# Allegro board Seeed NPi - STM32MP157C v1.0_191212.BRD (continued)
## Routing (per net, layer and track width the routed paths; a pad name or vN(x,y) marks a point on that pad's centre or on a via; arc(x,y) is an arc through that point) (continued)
SDMMC1_CK: length 3.2
  TOP w0.121: J10.38 30.61,45.6 30.59,45.57 C11.1 29.63,45.57 29.61,45.55 R37.1
SDMMC1_CMD: length 57.6
  TOP w0.121: J10.36 31.28,46 30.32,46.96 28.48,46.96 26.45,48.99 22.13,48.99 19.2,51.92 14.28,51.92 14.28,51.93 14.27,51.93 12.86,53.34 8.71,53.34 8.16,53.88 8.16,54.33 8.16,54.33 8.16,54.46 v1(7.91,54.71)
  LYR3 w0.121: v1(7.91,54.71) 7.66,54.96 7.66,56.62 7.91,56.87 7.91,62.94 14.84,69.87 14.84,77.36 14.51,77.7 14.51,79.54 v1(14.92,79.95)
  BOTTOM w0.121: R154.1 v1(14.92,79.95)
SDMMC1_D0: length 51.6
  TOP w0.121: v1(41.69,54.84) 41.18,54.33 37.24,54.33 36.36,53.44 34.32,53.44 33.56,52.67 33.56,47.88 33.28,47.6 J10.28
  LYR3 w0.121: v1(40.62,79.65) 40.62,78.94 40.44,78.76 40.1,78.76 39.98,78.88 39.98,79.4 39.86,79.52 39.62,79.52 39.5,79.4 39.5,78.88 39.38,78.76 39,78.76 38.77,78.53 38.77,77.87 38.89,77.75 39.05,77.75 39.17,77.63 39.17,77.39 39.05,77.27 38.89,77.27 38.77,77.15 38.77,76.88 38.65,76.76 38.36,76.76 38.24,76.64 38.24,76.4 38.36,76.28 38.65,76.28 38.77,76.16 38.77,75.76 38.08,75.08 37.91,75.08 37.73,75.26 37.56,75.26 37.39,75.09 37.39,74.92 37.57,74.74 37.57,74.57 37.4,74.39 37.4,74.05 37.28,73.93 37.14,73.93 37.02,73.81 37.02,73.56 37.14,73.44 37.28,73.44 37.4,73.32 37.4,73.08 37.28,72.96 37.14,72.96 37.02,72.84 37.02,72.6 37.14,72.48 37.28,72.48 37.4,72.36 37.4,72.12 37.28,72 37.14,72 37.02,71.87 37.02,71.63 37.14,71.51 37.28,71.51 37.4,71.39 37.4,71.07 38.01,70.46 40.09,70.46 41.33,69.21 41.33,68.81 41.21,68.69 41.07,68.69 40.95,68.57 40.95,68.33 41.07,68.21 41.21,68.21 41.33,68.09 41.33,67.84 41.21,67.72 41.07,67.72 40.95,67.6 40.95,67.36 41.07,67.24 41.21,67.24 41.33,67.12 41.33,64.77 41.05,64.49 41.05,57.5 41.69,56.87 v1(41.69,54.84)
  BOTTOM w0.121: v1(40.62,79.65) 40.62,80.04 R83.1
SDMMC1_D1: length 54.8
  TOP w0.121: v1(42.71,54.84) 41.95,54.08 37.35,54.08 36.39,53.12 34.39,53.12 33.81,52.54 33.81,50.6 33.82,50.59 33.82,47.72 33.29,47.2 J10.30
  LYR3 w0.121: v1(39.53,78.28) 39.53,77.91 39.65,77.79 39.94,77.79 40.06,77.67 40.06,77.43 39.94,77.31 39.65,77.31 39.53,77.19 39.53,76.95 39.65,76.83 39.94,76.83 40.06,76.7 40.06,76.46 39.94,76.34 39.65,76.34 39.53,76.22 39.53,75.92 37.75,74.14 37.75,71.35 38.13,70.96 40.42,70.96 41.69,69.69 41.69,64.3 41.57,64.18 41.48,64.18 41.36,64.06 41.36,63.82 41.48,63.7 41.57,63.7 41.69,63.58 41.69,63.33 41.57,63.21 41.48,63.21 41.36,63.09 41.36,62.85 41.48,62.73 41.57,62.73 41.69,62.61 41.69,62.37 41.57,62.25 41.48,62.25 41.36,62.13 41.36,61.89 41.48,61.77 41.57,61.77 41.69,61.65 41.69,61.4 41.57,61.28 41.48,61.28 41.36,61.16 41.36,60.92 41.48,60.8 41.57,60.8 41.69,60.68 41.69,60.44 41.57,60.32 41.48,60.32 41.36,60.2 41.36,59.96 41.48,59.84 41.57,59.84 41.69,59.71 41.69,59.47 41.57,59.35 41.48,59.35 41.36,59.23 41.36,58.99 41.48,58.87 41.57,58.87 41.69,58.75 41.69,58.39 41.44,58.14 41.44,57.52 42.1,56.87 42.1,56.62 42.22,56.5 44.31,56.5 44.43,56.38 44.43,56.14 44.31,56.01 43.71,56.01 43.59,55.89 43.59,55.34 43.47,55.22 43.23,55.22 43.1,55.34 43.1,55.89 42.98,56.01 42.22,56.01 42.1,55.89 42.1,55.06 42.32,54.84 v1(42.71,54.84)
  BOTTOM w0.121: R93.1 39.14,78.24 39.18,78.28 v1(39.53,78.28)
SDMMC1_D2: length 54.4
  TOP w0.121: v1(8.42,55.47) 8.67,55.22 8.67,54.07 8.82,53.92 12.98,53.92 14.48,52.42 19.67,52.42 22.51,49.58 26.61,49.58 28.73,47.47 30.51,47.47 31.18,46.8 J10.32
  LYR3 w0.121: v1(8.42,55.47) 8.42,62.71 15.48,69.78 16.82,69.78 17.81,70.77 17.81,75.98 17.89,76.06 v1(17.89,76.41)
  BOTTOM w0.121: v1(17.89,76.41) 17.9,76.42 R142.1
SDMMC1_D3: length 54.8
  TOP w0.121: v1(8.03,55.85) 8.03,55.22 8.42,54.84 8.42,53.98 8.78,53.62 12.93,53.62 14.37,52.17 14.38,52.17 14.38,52.17 19.46,52.17 22.39,49.25 26.58,49.25 28.61,47.22 30.42,47.22 31.23,46.4 J10.34
  LYR3 w0.121: v1(14.98,77.95) 14.98,77.6 15.13,77.45 15.13,69.8 8.16,62.84 8.16,56.77 8.03,56.64 v1(8.03,55.85)
  BOTTOM w0.121: R156.1 15.02,77.99 v1(14.98,77.95)
SDMMC3_CLK: length 47.1
  TOP w0.121: v1(33.69,39.09) 34.04,39.09 34.15,39.2 J10.69 ; R26.1 27.05,68.72 26.82,68.94 v1(26.65,68.94)
  LYR3 w0.121: v1(34.58,68.68) 34.58,68.33 34.04,67.79 34.04,64.39 36.36,62.07 36.36,59.59 39.78,56.17 39.78,48.55 38.86,47.63 36.38,47.63 35.5,46.74 35.5,40.26 34.32,39.09 v1(33.69,39.09)
  LYR4 w0.121: v1(26.65,68.94) 27.29,68.3 34.2,68.3 v1(34.58,68.68)
SDMMC3_CMD: length 46.3
  TOP w0.121: v1(34.2,39.6) J10.67 ; v1(26.65,69.71) R25.1
  LYR3 w0.121: v1(34.2,39.6) 34.96,40.36 34.96,44.68 35.28,45 35.28,46.84 36.29,47.85 38.77,47.85 39.53,48.61 39.53,56.11 36.12,59.51 36.12,61.93 33.82,64.23 33.82,68.45 34.45,69.09 v1(34.45,69.44)
  LYR4 w0.121: v1(34.45,69.44) 33.69,68.68 29.5,68.68 29.09,69.09 27.27,69.09 v1(26.65,69.71)
SDMMC3_D0: length 50.7
  TOP w0.121: J10.59 34.12,41.2 v1(33.56,41.75) ; R27.1 26.77,67.78 26.19,68.36 26.19,70.34 25.56,70.96 v1(25.56,71.35)
  LYR3 w0.121: v1(33.31,70.67) 32.8,70.16 32.8,62.95 33.53,62.22 33.53,61.66 34.96,60.23 34.96,59.28 38.01,56.23 38.01,48.99 37.86,48.85 36.71,48.85 36.56,48.99 34.96,48.99 32.95,46.98 32.95,44.29 33.94,43.3 33.94,42.14 v1(33.56,41.75)
  LYR4 w0.121: v1(33.31,70.67) 32.84,70.2 28.51,70.2 28,70.71 26.2,70.71 v1(25.56,71.35)
SDMMC3_D1: length 51
  TOP w0.121: R28.1 26.03,66.81 25.44,67.4 25.44,70.6 v1(24.8,71.24) ; J10.61 33.75,40.8 v1(33.69,40.74)
  LYR3 w0.121: v1(33.69,40.74) 34.2,41.25 34.2,44.93 34.58,45.31 34.58,47.09 36.1,48.61 38.01,48.61 38.26,48.87 38.26,56.36 35.21,59.41 35.21,60.42 34.83,60.8 34.83,61.57 34.83,61.57 34.83,61.6 33.05,63.37 33.05,69.16 v1(33.3,69.41)
  LYR4 w0.121: v1(33.3,69.41) 32.95,69.41 32.85,69.31 28.35,69.31 27.57,70.1 25.94,70.1 v1(24.8,71.24)
SDMMC3_D2: length 46.6
  TOP w0.121: J10.63 v1(34.11,40.4) ; R23.1 v1(26.65,71.64)
  LYR3 w0.121: v1(34.45,70.71) 34.2,70.46 34.07,70.46 33.82,70.2 33.82,69.31 33.31,68.81 33.31,63.47 35.09,61.69 35.09,60.93 35.47,60.55 35.47,59.53 38.51,56.49 38.51,50.14 39.02,49.63 39.02,48.74 38.64,48.36 36.16,48.36 34.83,47.03 34.83,45.18 34.45,44.8 34.45,40.74 v1(34.11,40.4)
  LYR4 w0.121: v1(26.65,71.64) 26.94,71.35 33.82,71.35 v1(34.45,70.71)
SDMMC3_D3: length 48.5
  TOP w0.121: J10.65 v1(33.69,40) ; R24.1 26.77,70.7 26.25,71.22 v1(26.25,71.32)
  LYR3 w0.121: v1(33.69,40) 34.24,40 34.7,40.46 34.7,44.74 35.05,45.09 35.05,46.93 36.23,48.1 38.7,48.1 39.31,48.71 39.31,56.01 35.9,59.41 35.9,61.39 33.56,63.73 33.56,68.68 34.07,69.19 34.07,69.69 v1(34.45,70.08)
  LYR4 w0.121: v1(26.25,71.32) 26.52,71.04 33.48,71.04 v1(34.45,70.08)
SPI5_CLK: length 24.7
  TOP w0.121: v1(37.12,43.91) 36.89,43.91 36.81,44 J10.45
  LYR3 w0.121: v1(50.47,41.92) 50.22,42.17 50.22,42.17 49.44,42.96 49.44,47.92 50.23,48.71 J19.23
  LYR4 w0.121: v1(37.12,43.91) 37.6,43.91 37.72,44.04 40.17,44.04 40.8,43.41 48.93,43.41 50.14,42.2 50.2,42.2 50.22,42.17 50.22,42.17 v1(50.47,41.92)
SPI5_MISO: length 28.9
  TOP w0.121: J19.21 52.39,50.1 52.39,42.94 v1(53.22,42.1) ; v1(36.71,44.37) 36.36,44.37 36.33,44.4 J10.43
  LYR4 w0.121: v1(53.22,42.1) 52.87,42.1 52.67,42.31 50.53,42.31 49.21,43.63 40.96,43.63 40.21,44.37 v1(36.71,44.37)
SPI5_MOSI: length 32.4
  TOP w0.121: J10.41 36.36,44.8 36.38,44.77 v1(37.12,44.77) ; v1(53.93,42.44) 53.41,42.44 52.64,43.21 52.64,52.4 J19.19
  LYR4 w0.121: v1(37.12,44.77) 40.19,44.77 41.05,43.91 49.31,43.91 50.69,42.53 53.31,42.53 53.41,42.44 v1(53.93,42.44)
SPI5_NSS: length 20.1
  TOP w0.121: v1(37.63,50.01) 37.21,49.6 J10.17 34.66,49.6
  LYR4 w0.121: v1(37.63,50.01) 37.87,50.26 40.57,50.26 40.95,49.88 47.91,49.88 48.04,50.01 52.48,50.01 J19.24
STLINK_SWCLK: length 78.8
  TOP w0.121: v1(13.5,73.89) 13.5,74.24 13.11,74.63 13.11,75.59 13.94,76.42 R111.2 ; J7.53 42.48,49.6 40.18,47.3 v1(40.18,45.69)
  LYR3 w0.121: v1(7.65,50.64) 4.35,50.64 3.72,51.28 3.72,63.24 9.16,68.68 12.54,68.68 13.5,69.63 v1(13.5,73.89)
  LYR4 w0.121: v1(7.65,50.64) 7.65,48.99 8.67,47.98 11.84,47.98 12.7,47.12 20.3,47.12 23,44.42 34.2,44.42 35.21,45.44 38.32,45.44 38.57,45.69 v1(40.18,45.69)
STLINK_SWDIO: length 80.9
  TOP w0.121: R101.2 15.47,76.42 14.72,75.67 13.78,75.67 13.5,75.38 13.5,74.9 v1(13.88,74.52) ; v1(39.78,45.31) 40.33,45.31 40.55,45.54 40.55,47.27 42.48,49.2 J7.51
  LYR3 w0.121: v1(7.53,51.41) 7.17,51.41 7.05,51.53 4.48,51.53 3.97,52.04 3.97,63.13 9.26,68.42 12.6,68.42 13.72,69.54 13.72,73.22 13.88,73.38 v1(13.88,74.52)
  LYR4 w0.121: v1(7.53,51.41) 7.15,51.03 7.15,48.1 9.18,46.07 12.48,46.07 13.31,46.9 18.48,46.9 20.44,44.93 21.62,44.93 22.39,44.17 34.26,44.17 35.27,45.18 39.3,45.18 39.43,45.31 v1(39.78,45.31)
SW: length 1.2
  BOTTOM w0.305: U9.6 v1(36.34,23.58)
  vias: v1(31.02,27.28) v1(31.02,26.77) v1(31.53,27.28) v1(31.53,26.77) v1(32.04,27.28) v1(32.04,26.77) v1(36.61,23.97) v1(36.86,23.59) v1(37.12,23.97)
TIM1_CH4: length 47.3
  TOP w0.121: J14.46 21.95,54.89 23.26,53.58 v1(23.26,52.18)
  LYR4 w0.121: v1(46.26,54.45) 43.59,54.45 42.96,53.82 39.02,53.82 37.38,52.18 v1(23.26,52.18)
  BOTTOM w0.121: J19.31 50.07,39.72 50.07,42.64 48.29,44.43 48.29,46.08 47.79,46.57 47.03,46.57 46.01,47.6 46.01,53.84 46.26,54.09 v1(46.26,54.45)
TIM4_CH3: length 19.4
  TOP w0.121: J7.35 41.99,46 41.43,45.43 41.43,42.01 v1(41.82,41.63)
  LYR4 w0.121: J19.32 52.36,39.98 50.2,39.98 48.55,41.63 v1(41.82,41.63)
TIM4_CH4: length 21.3
  TOP w0.121: v1(41.56,37.06) 41.18,37.44 41.18,45.56 42.01,46.4 J7.37
  LYR4 w0.121: v1(41.56,37.06) 42.6,36.01 J19.33
TIM5_CH4: length 50.2
  TOP w0.121: v1(18.45,54.45) 16.92,54.45 16.66,54.71 16.66,55.52 16.75,55.61 J14.20
  LYR4 w0.121: v1(18.45,54.45) 19.59,54.45 19.85,54.2 30.01,54.2 31.78,55.98 44.36,55.98 44.79,56.41 46.11,56.41 v1(46.36,56.16)
  BOTTOM w0.121: J19.29 51.24,42.11 48.57,44.77 48.57,46.17 47.92,46.82 47.16,46.82 46.77,47.21 46.77,54.84 46.36,55.25 v1(46.36,56.16)
UART4_RX: length 48
  TOP w0.121: v1(47.14,18.14) R97.2 46.76,18.8 46.73,18.77 44.74,18.77 44.48,19.03 U6.6 ; J10.27 36.56,47.6 37.07,47.09 37.17,47.09 v1(37.21,47.05)
  LYR3 w0.121: v1(48.17,30.07) 44.23,26.13 44.23,21.05 v1(47.14,18.14)
  BOTTOM w0.121: v1(37.21,47.05) 37.68,46.57 45,46.57 49.31,42.26 49.31,31.21 v1(48.17,30.07)
UART4_TX: length 39.2
  TOP w0.121: U6.5 44.98,19.41 45.12,19.28 46.65,19.28 47.15,19.78 R98.2 47.15,20.42 44.74,22.83 44.74,25.63 49.56,30.45 49.56,49.63 49.2,50 J7.56
USART1_CTS: length 31.7
  TOP w0.121: v1(38.13,43.62) 37.37,42.86 37.37,42.26 37.11,42 J10.55
  LYR3 w0.121: v1(38.13,43.62) 38.13,44.68 41.56,48.1 41.56,50.14 40.55,51.15 40.55,56.49 39.91,57.12 39.91,67.91 40.17,68.17 v1(40.17,68.57)
  BOTTOM w0.121: R79.1 40.42,68.94 40.17,68.68 v1(40.17,68.57)
USART1_RTS: length 37.8
  TOP w0.121: v1(38.13,43.02) 38.13,42.64 37.09,41.6 J10.57
  LYR3 w0.121: v1(38.77,69.69) 39.12,70.05 39.68,70.05 40.54,69.19 40.54,68.16 40.17,67.79 40.17,57.25 40.77,56.64 40.77,51.31 41.82,50.26 41.82,47.98 38.51,44.67 38.51,43.4 v1(38.13,43.02)
  BOTTOM w0.121: v1(38.77,69.69) 39.56,70.49 39.56,71.61 40.04,72.09 R76.1
USART1_RX: length 32.2
  TOP w0.121: J10.53 36.5,42.4 36.51,42.39 v1(36.86,42.39)
  LYR3 w0.121: v1(36.86,42.39) 37.75,43.28 37.75,44.68 41.28,48.2 41.28,48.33 41.31,48.36 41.31,50.01 40.29,51.02 40.29,56.36 39.66,56.99 v1(39.66,68.3)
  BOTTOM w0.121: v1(39.66,68.3) 39.66,68.4 39.78,68.52 39.78,69.44 40.42,70.08 R78.1
USART1_TX: length 33.6
  TOP w0.121: v1(38.01,46.2) 38.01,44.04 36.76,42.8 J10.51
  LYR3 w0.121: v1(39.45,69.61) 39.2,69.37 39.2,57.07 40.04,56.23 40.04,50.9 41.05,49.88 41.05,48.36 38.9,46.2 v1(38.01,46.2)
  BOTTOM w0.121: v1(39.45,69.61) 39.45,69.97 39.81,70.32 39.81,70.99 39.95,71.13 R77.1
USART2_CTS: length 59.5
  TOP w0.121: J14.48 22.35,55.1 24.04,53.42 24.04,52.32 v1(23.26,51.54)
  LYR4 w0.121: v1(52.48,54.45) 52.1,54.84 43.34,54.84 42.58,54.07 38.93,54.07 37.41,52.55 22.9,52.55 22.77,52.42 22.77,51.69 22.91,51.54 v1(23.26,51.54)
  BOTTOM w0.121: v1(52.48,54.45) 52.74,54.2 52.74,54.07 52.77,54.04 52.77,34.49 J19.36
USART2_RTS: length 21.3
  TOP w0.121: v1(48.28,48.22) 47.93,48.22 47.92,48.23 47.91,48.23 47.75,48.4 J7.48
  LYR3 w0.121: J19.11 52.51,62.68 52.51,60.42 52,59.92 50.71,59.92 48.67,57.88 48.67,53.82 49.18,53.31 49.18,50.77 48.28,49.87 v1(48.28,48.22)
USART2_RX: length 34.8
  TOP w0.121: J10.2 31.79,52.8 31.66,52.93 31.66,55.02 32.99,56.36 43.47,56.36 47.15,60.04 v1(48.93,60.04)
  LYR4 w0.121: J19.10 52.61,67.66 50.2,67.66 49.82,67.28 49.82,60.3 49.56,60.04 v1(48.93,60.04)
USART2_TX: length 35.9
  TOP w0.121: v1(49.31,60.55) 47.02,60.55 43.09,56.61 32.9,56.61 31.28,54.99 31.28,52.62 31.5,52.4 J10.4
  LYR4 w0.121: v1(49.31,60.55) 49.56,60.8 49.56,67.66 49.82,67.92 52.66,67.92 J19.8
USB1_EN: length 67.5
  TOP w0.121: v1(21.12,54.96) 21.12,55.31 21.13,55.33 21.13,55.35 21.15,55.37 J14.42 ; v1(24.16,23.59) 22.64,22.07 17.18,22.07 16.04,23.21 16.04,27.02 v1(15.27,27.78)
  LYR3 w0.121: v1(15.27,27.78) 11.08,31.98 11.08,35.23 9.05,37.26 v1(9.05,40.48)
  LYR4 w0.121: v1(21.12,54.96) 21.12,55.72 19.85,56.99 7.83,56.99 5.53,54.69 5.53,44.01 v1(9.05,40.48)
  BOTTOM w0.121: U12.3 24.06,23.69 v1(24.16,23.59) 24.19,23.56 R20.2
USB1_N: length 62.8
  TOP w0.114: J7.62 47.18,51.2 47.24,51.26 47.68,51.26 v1(47.91,51.03) ; v1(18.33,24.23) 18.58,24.47 18.58,30.58 20.1,32.1 23.91,32.1 27.59,35.79 38.51,35.79 38.99,35.31 38.99,34.92 v1(39.23,34.67)
  LYR3 w0.127: v1(39.23,34.67) 39,34.91 39,35.33 47.02,43.35 47.02,44.01 47.15,44.14 47.15,44.14 47.28,44.27 47.28,44.52 47.15,44.65 47.15,44.65 47.02,44.78 47.02,45.03 47.15,45.16 47.15,45.16 47.28,45.28 47.28,45.54 47.15,45.67 47.15,45.67 47.02,45.79 47.02,50.97 47.29,51.24 47.69,51.24 v1(47.91,51.03)
  BOTTOM w0.114: v1(18.33,24.23) 18.58,23.98 18.58,21.82 18.07,21.31 16.53,21.31 14.5,19.28 14.5,18.6 14.21,18.31 L4.1 14.12,17.69 R72.1
USB1_OC: length 53.4
  TOP w0.121: J14.40 20.75,55.61 20.73,55.59 v1(20.73,55.36)
  LYR4 w0.121: v1(17.94,28.29) 15.78,28.29 14.38,29.69 14.38,35.79 5.75,44.42 5.75,54.5 7.98,56.74 19.36,56.74 v1(20.73,55.36)
  BOTTOM w0.121: U12.8 17.53,26.23 17.81,26.51 17.81,27.6 17.56,27.85 R10.1 v1(17.94,28.29)
USB1_P: length 62.8
  TOP w0.114: v1(38.47,34.67) 38.71,34.92 38.71,35.19 38.4,35.51 37.57,35.51 37.46,35.39 37.46,35.26 37.34,35.15 37.12,35.15 37,35.26 37,35.39 36.89,35.51 36.66,35.51 36.54,35.39 36.54,35.26 36.43,35.15 36.2,35.15 36.09,35.26 36.09,35.39 35.97,35.51 27.71,35.51 24.03,31.82 20.22,31.82 18.85,30.46 18.85,24.47 v1(19.1,24.23) ; v1(47.91,51.79) 47.66,51.54 47.24,51.54 47.18,51.6 J7.64
  LYR3 w0.127: v1(47.91,51.79) 47.67,51.55 47.17,51.55 46.72,51.1 46.72,43.48 38.7,35.46 38.7,34.91 v1(38.47,34.67)
  BOTTOM w0.114: R80.1 15.13,17.72 L4.4 15.06,18.31 14.78,18.6 14.78,19.16 16.65,21.03 18.18,21.03 18.85,21.7 18.85,23.98 v1(19.1,24.23)
USB2_EN: length 49.4
  TOP w0.121: J7.52 48.47,49.2 49.31,48.36 49.31,36.67 44.99,32.36 v1(41.31,32.36)
  LYR4 w0.121: v1(41.31,32.36) 33.43,24.48 26.7,24.48 24.16,21.94 v1(23.78,21.94)
  BOTTOM w0.121: U12.4 23.3,22.42 v1(23.78,21.94) 23.82,21.91 R17.2
USB2_N: length 60
  TOP w0.114: v1(48.37,52.21) 48.13,52.46 47.24,52.46 47.18,52.4 J7.68 ; v1(29.12,33.84) 28.87,34.1 27.82,34.1 24.53,30.81 22.6,30.81 22.49,30.69 22.49,30.62 22.37,30.5 22.14,30.5 22.03,30.62 22.03,30.69 21.91,30.81 21.49,30.81 21.15,30.47 21.15,30.15 20.98,29.99 20.67,29.99 19.97,29.29 19.97,23.46 v1(20.22,23.21)
  LYR3 w0.127: v1(48.37,52.21) 48.14,52.44 46.46,52.44 46.06,52.04 46.06,44.17 35.97,34.08 29.36,34.08 v1(29.12,33.84)
  BOTTOM w0.114: v1(20.22,23.21) 19.97,22.97 19.97,21.05 18.93,20.01 17.79,20.01 16.94,19.16 16.94,18.6 17.22,18.31 L5.2 17.24,17.77 R86.2
USB2_OC: length 61.9
  TOP w0.121: J7.50 48.24,48.8 49.06,47.97 49.06,36.81 44.99,32.74 v1(40.67,32.74)
  LYR4 w0.121: v1(40.67,32.74) 32.64,24.7 26.54,24.7 24.16,22.32 15.78,22.32 14.01,20.55 v1(14.01,19.53)
  BOTTOM w0.121: v1(14.01,19.53) R9.1 14.01,20.61 14,20.61 14,20.93 15.5,22.42 U12.5
USB2_P: length 60
  TOP w0.114: v1(29.12,34.63) 28.87,34.38 27.71,34.38 24.42,31.09 21.37,31.09 19.69,29.41 19.69,23.46 v1(19.45,23.21) ; J7.70 47.18,52.8 47.24,52.74 48.13,52.74 v1(48.37,52.98)
  LYR3 w0.127: v1(29.12,34.63) 29.36,34.39 35.85,34.39 45.75,44.29 45.75,52.17 46.33,52.75 48.14,52.75 v1(48.37,52.98)
  BOTTOM w0.114: v1(19.45,23.21) 19.69,22.97 19.69,21.17 18.82,20.29 17.67,20.29 16.66,19.28 16.66,18.6 16.37,18.31 L5.3 16.28,17.69 R87.2
VETH1_AVDDH: length 33.6
  TOP w0.305: v1(28.1,33.12) 28.1,32.67 27.85,32.42 27.85,25.75 27.21,25.12 27.21,20.55 23.83,17.17 23.83,13.89 28.89,8.83 v1(29.55,8.83)
  BOTTOM w0.305: U5.47 v1(20.59,41.99) ; U5.12 13.46,40.32 v1(13.24,40.1) ; U5.1 18.96,39.96 19.63,39.29 C52.1 20.36,39.29 v1(20.36,39.29)
  BOTTOM w0.381: R103.1 v1(29.55,8.83)
  vias: v1(28.1,33.63)
VETH1_AVDDL: length 1.4
  BOTTOM w0.305: U5.9 v1(14.96,40.1) ; U5.4 v1(17.46,40.07)
  vias: v1(14.26,38.58) v1(14.77,38.58)
VETH1_AVDDL_PLL: length 5.2
  BOTTOM w0.305: C43.1 23.47,43.71 C42.1 C41.1 20.91,43.71 20.69,43.49 U5.44
  BOTTOM w0.381: C43.1 23.61,43.69 FB9.2
VETH1_AVDDL_PMOS: length 2
  BOTTOM w0.381: v1(12.58,52.65) FB6.1 v1(13.06,52.24) ; v1(12.62,38.08) 12.63,38.07 12.86,38.07 12.95,37.98 R109.1 v1(13.11,38.58)
  vias: v1(25.18,43.02) v1(25.18,42.52) v1(25.69,42.52)
VETH1_DVDDH: length 64.3
  TOP w0.305: v1(29.6,7.95) 29.14,7.95 23.4,13.69 23.4,17.62 26.7,20.93 26.7,25.37 27.34,26.01 27.34,28.67 v1(26.2,29.82)
  LYR3 w0.305: v1(23.91,32.86) 23.91,32.1 v1(26.2,29.82)
  LYR3 w0.381: v1(23.91,32.86) 23.91,45.59 v1(23.1,46.4)
  BOTTOM w0.305: R89.1 22.31,45.69 R94.2 ; R108.1 22.35,37.31 22.89,36.76 22.89,35.79 22.5,35.39 U8.5 22.5,33.39 23.03,32.86 v1(23.91,32.86) C62.1 ; v1(29.6,7.95) R104.1 R102.1 ; U5.34 v1(17.96,48.46) ; R107.2 v1(10.12,43.28) R106.2 ; U5.40 v1(20.41,45.49) ; U5.16 v1(12.13,42.99)
  BOTTOM w0.381: R66.2 v1(17.86,50.72) ; R70.2 v1(18.88,50.69) ; R68.2 15.83,50.69 v1(15.91,50.77) ; R64.2 v1(14.82,50.72) ; R85.1 R74.1 v1(24.34,48.43) ; R69.2 v1(16.85,50.72) ; R65.2 13.8,50.59 13.75,50.64 v1(13.75,50.77) ; C34.1 v1(22.69,49.96) ; R89.1 v1(23.1,46.4) ; C30.1 22.3,50.99 22.64,50.64 v1(22.64,50.39)
VETH1_DVDDL: length 5.4
  BOTTOM w0.305: U5.26 13.96,48.18 13.66,48.49 13.26,48.49 v1(13.25,48.48) ; U5.18 v1(12.15,43.99) ; U5.14 v1(12.11,41.99) ; v1(20.35,46) 20.35,45.99 U5.39 ; U5.30 v1(15.96,48.49) ; U5.23 v1(12.14,46.49)
  BOTTOM w0.381: v1(12.79,48.69) 12.79,48.82 12.48,49.12 C33.1
WL_HOST_WAKE: length 35.9
  TOP w0.121: R19.2 19.85,74.39 v1(19.34,74.39) ; v1(30.13,72.49) 30.65,71.97 U3.13 ; J14.28 18.35,55.48 18.24,55.36 v1(17.89,55.36)
  LYR3 w0.121: v1(17.89,55.36) 17.89,59.73 19.34,61.19 19.34,64.23 19.85,64.74 19.85,69.31 19.34,69.82 v1(19.34,74.39)
  BOTTOM w0.121: v1(19.34,74.39) 19.59,74.14 21.12,74.14 21.5,73.76 21.5,72.87 21.88,72.49 v1(30.13,72.49)
WL_REG_ON: length 21.3
  TOP w0.121: R133.1 19.84,73 v1(19.85,73) ; v1(18.45,54.96) 18.58,54.96 18.75,55.14 J14.30
  LYR3 w0.121: v1(19.85,73) 19.62,72.77 19.62,69.85 20.1,69.37 20.1,64.61 19.59,64.11 19.59,61.06 18.19,59.66 18.19,55.85 18.45,55.6 v1(18.45,54.96)
N303234: length 8.1
  BOTTOM w0.381: R104.2 29.03,7.18 J13.11
N303238: length 8.2
  BOTTOM w0.381: R102.2 32.36,7.18 J13.14
N303440: length 6.6
  BOTTOM w0.121: X3.1 23.09,39.29 C51.2 22.5,39.29 22.26,39.53 22.26,39.9 21.61,40.56 R100.2 21.49,40.56 20.99,41.06 20.99,42.14 20.63,42.49 U5.46
N303536: length 8
  BOTTOM w0.121: U5.45 20.51,42.99 21.55,41.96 R100.1 21.61,41.32 22.14,40.8 22.26,40.8 22.5,40.56 C47.2 22.62,40.56 23.15,40.04 24.93,40.04 25.65,40.76 X3.3
N303624: length 8
  BOTTOM w0.381: J13.5 31.33,14.74 J13.6 31.33,12.45 31.17,12.3 C48.1 R103.2
N303732: length 2.6
  BOTTOM w0.121: U8.2 21.85,31.44 21.47,31.06 R128.2 R129.2
N3772447: length 8.9
  TOP w0.121: v1(38.26,69.19) 37.12,69.19 36.74,68.81 36.74,64.26 37.4,63.6 U3.28
  BOTTOM w0.121: v1(38.26,69.19) 38.84,69.19 TP6.1
N3772513: length 10.2
  TOP w0.121: U3.27 36.5,63.47 36.36,63.62 36.36,69.57 v1(36.86,70.08)
  BOTTOM w0.121: TP5.1 38.26,70.33 37.12,70.33 v1(36.86,70.08)
N3772517: length 7.2
  TOP w0.121: U3.26 35.6,63.47 35.6,63.48 35.6,65.76 35.9,66.06 v1(35.9,69.03)
  BOTTOM w0.121: v1(35.9,69.03) TP9.1
N3772521: length 9.2
  TOP w0.121: v1(35.85,70.08) 35.35,69.58 35.35,64.24 34.7,63.59 U3.25
  BOTTOM w0.121: TP8.1 36.1,70.58 36.1,70.32 v1(35.85,70.08)
N3772562: length 2.9
  TOP w0.121: v1(38.13,75.66) 38.39,75.66 39.2,74.85 U3.4
  BOTTOM w0.121: TP7.1 38.31,75.66 v1(38.13,75.66)
N3774700: length 5.6
  TOP w0.254: X1.1 24.82,72.69 25.78,73.65 28.02,73.65 28.38,73.29 C9.1 28.5,73.29 28.86,72.93 28.86,72.93 29.28,72.52 R30.2
N3775644: length 5.4
  TOP w0.381: R49.2 41.94,76.15 arc(41.28,75.87) 41,75.2 U3.2
N3776012: length 12.4
  TOP w0.121: v1(21.95,73.05) 21.5,73.5 R133.2 20.75,73.64 R22.2 ; v1(30.26,73.12) 30.51,72.87 U3.12
  BOTTOM w0.121: v1(30.26,73.12) 22.38,73.12 22.31,73.05 v1(21.95,73.05)
N3776054: length 4.5
  TOP w0.121: R23.2 27.91,71.58 28.33,71.16 29.45,71.16 29.87,71.57 ; U3.14 30.37,71.07 29.87,71.57 ; 29.87,71.57 R31.1
N3776279: length 4.5
  TOP w0.121: 29.87,70.61 30.41,70.61 30.85,70.17 U3.15 ; 29.87,70.61 29.46,70.19 28.36,70.19 27.91,70.64 R24.2 ; 29.87,70.61 R32.1
N3776286: length 4.4
  TOP w0.121: U3.16 30.69,69.27 30.26,69.7 R33.1 29.88,69.64 29.47,69.23 28.33,69.23 27.91,69.65 R25.2
N3776293: length 4.4
  TOP w0.121: R26.2 27.91,68.66 28.35,68.22 29.46,68.22 29.89,68.65 R34.1 30.27,68.71 30.61,68.37 U3.17
N3776300: length 4.4
  TOP w0.121: R27.2 27.91,67.72 28.37,67.26 29.46,67.26 29.89,67.69 R35.1 30.27,67.75 30.55,67.47 U3.18
N3776307: length 4.5
  TOP w0.121: U3.19 30.49,66.57 30.28,66.78 R36.1 29.9,66.46 29.74,66.31 28.36,66.31 27.91,66.75 R28.2
N3776951: length 2.7
  TOP w0.121: R38.1 34.3,60.58 33.8,61.08 U3.24
N3777387: length 3.1
  TOP w0.121: R42.1 39.75,60.21 38.3,61.66 U3.29
N3779189: length 6.2
  TOP w0.381: R51.1 44.82,75.38 45.82,74.38 arc(46.74,73) 47.07,71.38 C22.1 47.05,70.76 R52.2
N3779193: length 2.6
  TOP w0.381: J16.1 47.05,67.37 47.05,67.37 C21.1 47.05,68.3 R52.1
N3780208: length 5.2
  TOP w0.381: ANT1.1 46.42,80.37 46.41,80.36 R50.1 47.42,76.91 C23.1
N3780222: length 1.9
  TOP w0.381: R49.1 45.53,76.14 R50.2 47.13,76.14 arc(47.29,76.11) C24.1
N3787372: length 56.5
  TOP w0.121: J7.55 44.48,50 44.86,50.38 44.86,53.57 45.12,53.83 v1(49.31,53.83)
  LYR3 w0.121: v1(49.69,17.62) 47.53,19.78 46.26,19.78 44.61,21.43 44.61,25.88 48.99,30.26 48.99,49.06 49.56,49.62 49.56,53.58 v1(49.31,53.83)
  BOTTOM w0.121: TP2.1 52.71,14.6 v1(49.69,17.62)
N3787386: length 1.6
  TOP w0.121: J7.57 v1(44.35,50.4)
  BOTTOM w0.121: TP15.1 44.97,50.4 v1(44.35,50.4)
N3787400: length 55.7
  TOP w0.121: v1(49.31,54.45) 48.93,54.07 44.86,54.07 44.48,53.69 44.48,51.03 44.25,50.8 J7.59
  LYR3 w0.121: v1(49.31,54.45) 49.82,53.95 49.82,49.57 49.21,48.96 49.21,30.1 44.83,25.72 44.83,21.72 46.55,20.01 47.94,20.01 v1(49.69,18.26)
  BOTTOM w0.121: TP1.1 51.44,16.51 v1(49.69,18.26)
N3793884: length 2.1
  TOP w0.508: U3.21 30.57,64.77 30.54,64.74 L1.1
N3794135: length 12
  TOP w0.508: L1.2 27.13,63.93 v1(27.85,63.22) ; v1(33.31,60.55) 33.31,61.1 32.9,61.5 U3.23
  LYR4 w0.508: v1(33.31,60.55) 32.76,60.55 32.63,60.68 29.88,60.68 28.67,61.89 28.67,62.4 v1(27.85,63.22)
  BOTTOM w0.508: v1(33.31,60.55) 33.31,60.46 33.96,59.81 C49.1
N3820313: length 10
  LYR4 w0.305: v1(36.79,50.09) 32.11,50.09 31.53,49.5 28.61,49.5 v1(28.35,49.25)
  BOTTOM w0.305: R67.2 v1(36.79,50.09) ; C29.1 28.43,49.32 v1(28.35,49.25)
N3820535: length 22.5
  LYR4 w0.406: v1(23.9,50.02) 24.4,50.02 24.51,50.14 31.15,50.14 32.42,51.41 v1(34.2,51.41) 36.11,51.41 36.23,51.52 36.88,51.52 v1(37.5,50.9)
  BOTTOM w0.305: R75.1 36.19,51.99 36.82,51.36 36.93,51.36 37.08,51.21 37.18,51.21 v1(37.5,50.9)
  BOTTOM w0.406: C46.1 23.61,54.41 23.4,54.2 23.4,52.77 23.9,52.27 v1(23.9,50.02) ; U4.5 v1(34.2,51.41)
N3820638: length 3.5
  BOTTOM w0.305: U4.7 34.53,50.11 35.4,50.98 R71.1 35.4,52.03 R75.2
N3835690: length 10
  TOP w0.508: R110.1 v1(18.7,19.4)
  LYR3 w0.508: v1(18.7,19.4) v1(18.19,19.4) 18.16,19.4 16.79,18.04 J8.A4
N3835694: length 2.6
  TOP w0.508: R114.1 20.73,19.72 20.3,19.28 19.98,19.28 v1(19.59,18.89)
  vias: v1(19.62,19.35)
N3854640: length 2.6
  TOP w0.508: J11.14 31.5,78.23 31.53,78.2 ; 32.42,78.08 32.5,78.16 J11.15
N3854714: length 3.3
  BOTTOM w0.381: J22.15 7.58,58.07 7.78,58.26 ; J22.16 7.61,59.07 7.65,59.03
N3873950: length 3
  TOP w0.508: J2.B12 7.13,35.51 7.65,36.04 v1(7.65,36.42) ; J2.B1 6.5,29.05 v1(7.78,29.05)
  vias: v1(7.53,36.93) v1(7.78,28.55) v1(8.03,36.93) v1(8.29,29.05)
N3874122: length 8.2
  TOP w0.381: J2.B4 5.83,29.86 5.18,30.52 ; 5.42,34.16 5.93,34.66 J2.B9
  TOP w0.508: J2.B9 7.25,34.66 v1(7.53,34.39) ; 5.18,30.52 4.66,31.04 4.66,33.4 5.42,34.16
  vias: v1(7.53,34.9) v1(8.03,34.9) v1(8.03,34.39) v1(8.54,34.9) v1(8.54,34.39)
N3911606: length 9.8
  TOP w0.121: v1(11.84,77.82) 11.5,78.17 SW3.3 SW3.1 ; R167.1 v1(15.5,75.76)
  LYR4 w0.121: v1(11.84,77.82) 12.23,77.82 14.28,75.76 v1(15.5,75.76)
N3915722: length 2.5
  TOP w0.121: Q3.3 12.89,64.84 12.82,64.77 R5.1 12.32,64.77 12.01,65.08 11.89,65.08 11.45,65.52 R3.1
N3915999: length 2.9
  TOP w0.121: Q2.3 13.46,68.07 12.86,67.47 12.78,67.47 12.46,67.16 R7.1 12.34,67.16 12.03,66.85 11.94,66.85 11.76,66.67 11.76,66.61 11.45,66.3 R8.1
N3917680: length 6.5
  TOP w0.121: R15.2 16.8,71.35 17.56,70.58 20.35,70.58 20.57,70.8 J9.2
N3931666: length 5.8
  BOTTOM w0.254: 3.4,76 CON1.4 3.4,73.94 3.74,73.61 R176.2
N3973979: length 9.1
  TOP w0.121: J9.5 20.57,68.59 18.83,70.33 R16.1
N3987111: length 9.1
  TOP w0.121: R1.2 v1(1.91,17.09) ; v1(3.21,9.88) 3.21,9.13 LED1.1
  BOTTOM w0.121: v1(1.91,17.09) 1.91,11.17 v1(3.21,9.88)
N3987115: length 1.1
  TOP w0.121: R1.1 2.68,15.82 Q1.3
N3990987: length 4.3
  BOTTOM w0.121: 35.38,50.02 34.81,49.46 U4.8 ; 35.38,50.02 R67.1 ; 35.38,50.02 35.38,49.56 35.36,49.54 R161.1 35.36,48.56 35.34,48.55 R160.2
N3991147: length 5.6
  BOTTOM w0.121: C19.1 35.34,47.15 35.1,47.39 35.1,47.4 TP4.1 33.75,48.18 33.7,48.23 32.8,48.23 31.57,49.46 U4.1
N3991771: length 2.4
  BOTTOM w0.381: L2.1 34.34,54.47 34.7,54.84 v1(34.71,54.84)
  BOTTOM w0.406: U4.3 v1(29.62,50.76)
  vias: v1(28.74,51.28) v1(29.12,50.77) v1(29.24,51.28) v1(34.7,54.33) v1(34.7,53.82) v1(35.21,54.84) v1(35.21,54.33) v1(35.21,53.82)
N4046258: length 34
  LYR4 w0.305: v1(17.12,66.84) 18.12,65.83 26,65.83 27.85,63.98 39.61,63.98 v1(44.05,59.53)
  BOTTOM w0.203: U11.4 41.77,58.98
  BOTTOM w0.305: v1(44.05,59.53) 43.7,59.18 R126.1 41.97,59.18 41.77,58.98 ; C74.2 v1(17.12,66.84)
N4046262: length 5.1
  BOTTOM w0.254: U11.32 40.28,61.56 40.55,61.82
  BOTTOM w0.381: 40.55,61.82 41.06,62.33 C79.1 41.06,64.86 C78.1 41.05,65.96 R131.2
N4046268: length 8.2
  BOTTOM w0.203: U11.10 39.78,55.6 39.93,55.45 40.66,55.45 ; 41.72,56.71 41.6,56.71 41.34,56.97 U11.8
  BOTTOM w0.406: R117.2 45.18,56.65 C72.1 44.1,56.64 C76.1 42.2,56.64 ; 41.72,56.71 41.79,56.64 42.2,56.64 ; 42.2,56.64 42.2,56.11 41.55,55.45 40.66,55.45
N4046299: length 10.2
  BOTTOM w0.254: U11.21 35.34,58.98 35.09,59.24 35.09,62.07 36.99,62.07 37.28,61.78 U11.26
  BOTTOM w0.381: R165.2 32.15,62.76 C95.1 33.32,62.68 C93.1 34.61,62.68 35.09,62.21 35.09,62.07
N4056572: length 5.1
  LYR4 w0.121: v1(37.5,53.17) 37.5,53.8 38.54,54.84 v1(38.89,54.84)
  BOTTOM w0.121: R152.1 37.35,53.34 37.5,53.18 v1(37.5,53.17) ; U11.13 38.28,55.45 38.64,55.09 38.64,55.09 v1(38.89,54.84) 39.15,54.58 R145.2
N4056576: length 2.4
  BOTTOM w0.121: U11.12 38.78,55.58 39.67,54.7 39.74,54.7 39.98,54.46 R140.2
N4056580: length 1.9
  BOTTOM w0.121: U11.16 36.78,54.88 36.48,54.58 R157.2
N4056584: length 2
  BOTTOM w0.121: U11.14 37.78,54.88 38.2,54.46 R148.2
N4056588: length 2.9
  BOTTOM w0.121: U11.11 39.28,55.46 39.78,54.96 40.44,54.96 40.97,54.43 R137.2
N4058145: length 1.8
  BOTTOM w0.121: U11.15 37.28,54.62 37.35,54.56 R152.2
N4058376: length 6.5
  BOTTOM w0.254: U11.27 37.78,62.17 37.12,62.84 36.61,62.84
  BOTTOM w0.381: C92.1 34.2,64.38 C90.1 34.72,63.29 35.17,62.84 36.61,62.84
N4058385: length 4.6
  BOTTOM w0.203: U11.1 41.64,60.48
  BOTTOM w0.305: 41.64,60.48 41.77,60.61 C75.1 43.83,60.61 C70.1 45.33,60.96 R116.1
N4059055: length 1.4
  BOTTOM w0.254: U11.30 39.28,62.4 TP16.1
N4059075: length 3.2
  BOTTOM w0.254: U11.31 39.78,62.84 39.34,63.28 C81.1
N4059079: length 3.7
  BOTTOM w0.254: U11.29 38.78,62 38.06,62.72 38.06,63.3 37.18,64.17 C84.1
N4059170: length 9.6
  BOTTOM w0.305: C81.2 39.23,67.05 38.13,68.14 33.94,68.14 33.06,67.27 R4.1 C4.1 30.64,67.27 FB1.1
N4059174: length 7.4
  BOTTOM w0.305: C84.2 35.97,66.99 35.31,67.66 34.07,67.66 32.62,66.21 R6.1 C5.1 30.78,66.21 FB2.1
N4060621: length 2.8
  BOTTOM w0.305: C74.1 16.66,64.88 16.05,65.49 C71.1 15.98,65.45 15.43,64.9 FB11.2
N4439955: length 21.2
  TOP w0.121: 43.87,14.83 D9.1 43.87,15.84 43.98,15.95 U6.2 ; 43.87,14.83 42.45,14.83 42.07,15.21 42.07,17.11 42.08,17.12 R96.1 42.08,17.62 41.66,18.04 41.66,18.23 41.35,18.54 R91.1 ; 43.87,14.83 43.87,13.41 44.61,12.67 49.62,12.67 J24.1
N4439995: length 17.8
  TOP w0.121: U6.3 44.48,16.08 44.72,15.85 D8.1 44.72,13.71 45.37,13.05 50.33,13.05 v1(52.1,11.27)
  BOTTOM w0.121: J24.2 52.1,7.65 v1(52.1,11.27)
N4458088: length 8.4
  TOP w0.121: v1(16.16,77.19) 15.53,77.19 R101.1
  BOTTOM w0.121: TP10.1 13.59,82.31 13.55,82.28 D20.1 13.55,80.91 14.01,80.46 14.01,80.31 14.25,80.07 R112.2 14.25,77.96 15.15,77.06 16.04,77.06 v1(16.16,77.19)
N4458139: length 8.4
  TOP w0.121: v1(13.95,77.19) 14.07,77.19 14.07,77.19 R111.1
  BOTTOM w0.121: TP11.1 11.55,82.31 11.8,82.07 D21.1 11.8,80.91 11.31,80.42 11.31,80.31 11.07,80.07 R113.2 11.07,79.57 13.45,77.19 v1(13.95,77.19)
N4473305: length 9.7
  TOP w0.381: U1.5 v1(13.25,17.51)
  TOP w0.813: R88.2 v1(10.19,15.72) 10.19,14.45 9.79,14.05 J8.A1
  LYR4 w0.381: v1(13.25,17.51) 11.46,15.72 v1(10.19,15.72)
N4473534: length 15.5
  TOP w0.381: U7.5 v1(17.79,17.5)
  TOP w0.813: R90.1 v1(12.23,15.72) 12.23,14.32 11.1,13.2 11.1,10.63 J8.B1
  LYR4 w0.381: v1(17.79,17.5) 14,17.5 v1(12.23,15.72)
N4505708: length 2.1
  BOTTOM w0.203: U11.5 41.99,58.48
  BOTTOM w0.305: R126.2 42.48,57.98 41.99,58.48
N4522056: length 3.2
  TOP w0.121: v1(14.13,72.36) R12.1 R11.2
  BOTTOM w0.121: Q9.3 14.4,72.1 v1(14.13,72.36)
N4540641: length 9.4
  TOP w0.305: v1(31.78,23.58) 32.56,23.58 33.81,22.33 33.81,20.68 34.2,20.29 36.36,20.29 v1(36.86,19.78)
  BOTTOM w0.305: v1(36.86,19.78) 36.29,19.78 R127.2 ; U9.3 v1(31.78,23.58)
N4540827: length 18.8
  TOP w0.305: v1(34.27,21.26) 40.24,21.26 41.82,22.83 41.82,26.58 v1(45.69,30.45)
  BOTTOM w0.305: R139.1 v1(34.27,21.26) ; C53.1 v1(45.69,30.45)
N4540887: length 12.2
  TOP w0.305: v1(30.42,18.67) 34.36,18.67 v1(35.21,19.53)
  BOTTOM w0.305: U9.2 31.08,22.93 31.05,22.9 C54.1 v1(30.42,18.67) ; v1(35.21,19.53) R138.1
N4540895: length 2.5
  BOTTOM w0.254: U9.8 34.66,22.28 34.45,22.07 34.45,21.71 35.21,20.95 R138.2
N4541105: length 2.4
  BOTTOM w0.305: U9.1 32.24,22.28 32.03,22.06 32.03,21.43 32.32,21.14 R144.1
N4541109: length 2
  BOTTOM w0.305: R144.2 R147.1 R139.2
N4588094: length 4.4
  TOP w0.121: LED2.1 30.83,21.83 30.22,22.45 28.35,22.45 v1(27.82,21.92)
  BOTTOM w0.121: R13.2 v1(27.82,21.92)
N4589189: length 6.4
  TOP w0.121: LED3.1 32.36,22.13 31.53,22.96 28.23,22.96 v1(27.85,22.58)
  BOTTOM w0.121: v1(27.85,22.58) 27.8,22.58 R14.2
N4589271: length 2
  TOP w0.121: LED5.1 28.18,21.26 v1(27.85,20.93)
  BOTTOM w0.121: R134.2 27.51,20.93 v1(27.85,20.93)
N4607134: length 3.8
  TOP w0.305: R162.2 3.78,18.39 3.76,18.36 LED4.1

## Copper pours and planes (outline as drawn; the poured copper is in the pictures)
3V3_DC on TOP: 28.1,76.55 27.08,76.55 26.96,76.43 26.83,76.43 26.7,76.3 26.7,76.04 27.08,75.66 28.1,75.66 28.35,75.92 28.35,76.3
3V3_DC on BOTTOM: 11.84,56.99 12.61,56.99 12.86,56.74 12.86,55.47 12.61,55.22 11.84,55.22 11.59,55.47 11.59,56.74
3V3_DC on BOTTOM: 25.05,29.31 24.29,29.31 24.04,29.05 24.04,28.17 24.16,28.04 25.05,28.04 25.31,28.29 25.31,29.05
3V3_DC on BOTTOM: 21.37,52.8 20.61,52.8 20.48,52.68 20.48,51.79 20.61,51.66 21.37,51.66 21.5,51.79 21.5,52.68
3V3_DC on BOTTOM: 45.5,73.76 44.36,73.76 43.98,73.38 43.98,72.74 44.1,72.62 45.63,72.62 45.75,72.74 45.75,73.5
3V3_DC on BOTTOM: 24.16,64.74 26.83,64.74 27.47,64.11 27.47,57.12 26.83,56.49 25.56,56.49 25.05,56.99 25.05,61.95 24.8,62.2 20.61,62.2 20.1,62.71 20.1,66.65 20.35,66.9 21.88,66.9 22.13,66.65 22.13,64.36 21.88,64.11 21.88,63.85 22.13,63.6 23.02,63.6
3V3_DC on BOTTOM: 38.26,73.25 39.66,73.25 39.78,73.12 39.78,72.49 39.28,71.98 38.13,71.98 38.01,72.11 38.01,73
3V3_DC on LYR4: 45.5,73.63 38.9,73.63 38.39,73.12 38.39,71.22 38.64,70.96 43.98,70.96 44.61,71.6 44.61,72.49 44.74,72.62 45.5,72.62 45.63,72.74 45.63,73.5
3V3_DC on LYR5_PWR: 40.42,76.68 40.04,77.06 23.4,77.06 21.88,75.54 21.88,72.87 22.64,72.11 22.64,70.96 20.1,68.42 20.1,62.84 19.72,62.46 9.43,62.46 5.75,58.77 5.75,46.07 6,45.82 7.53,45.82 7.78,46.07 7.78,53.31 9.81,55.34 12.61,55.34 14.38,57.12 15.91,57.12 16.42,56.61 16.42,54.84 16.8,54.45 19.34,54.45 20.35,53.44 20.35,51.91 20.73,51.53 22.89,51.53 25.05,49.37 25.05,45.31 24.04,44.29 24.04,28.17 24.29,27.91 27.72,27.91 28.23,28.42 28.23,71.73 30.01,73.5 36.23,73.5 36.48,73.25 36.48,58.01 38.77,55.72 45.25,55.72 46.13,56.61 46.13,59.03 45.63,59.53 40.04,59.53 39.28,60.3 39.28,64.49 41.31,66.52 41.31,71.47 40.42,72.36
3V3_RPI on BOTTOM: 51.6,55.47 48.55,55.47 45.88,58.14 45.88,62.2 45.75,62.33 44.99,62.33 44.23,63.09 44.23,65.76 43.59,66.39 43.59,68.81 44.23,69.44 44.23,71.85 44.86,72.49 45.75,72.49 46.01,72.23 46.01,69.57 45.63,69.19 45.63,63.73 46.01,63.34 46.52,63.34 47.02,62.84 47.02,58.9 48.67,57.25 51.6,57.25 51.98,56.87 51.98,55.85
3V3_RPI on BOTTOM: 45.63,74.39 45.25,74.01 43.98,74.01 43.85,74.14 43.85,75.16 44.1,75.41 45.37,75.41 45.63,75.16
3V3_RPI on LYR4: 51.6,77.44 49.82,77.44 48.04,75.66 44.23,75.66 43.85,75.28 43.85,74.14 43.98,74.01 45.5,74.01 45.75,73.76 45.75,72.62 45.63,72.49 44.99,72.49 44.86,72.36 44.86,71.6 44.99,71.47 46.39,71.47 50.58,75.66 51.6,75.66 51.98,76.04 51.98,77.06
3V3_SYS on TOP: 44.23,40.87 44.99,40.87 45.25,40.61 45.25,38.96 45.75,38.45 48.04,38.45 48.29,38.2 48.29,36.8 47.91,36.42 43.21,36.42 42.32,37.31 42.32,38.83 42.71,39.21 43.98,39.21 44.1,39.34 44.1,40.74
3V3_SYS on BOTTOM: 37.24,73.25 36.1,73.25 35.59,72.74 35.59,72.11 35.72,71.98 37.12,71.98 37.5,72.36 37.5,73
3V3_SYS on BOTTOM: 19.08,66.9 18.19,66.9 17.69,66.39 17.69,63.47 18.19,62.96 19.08,62.96 19.34,63.22 19.34,66.65
3V3_SYS on LYR5_PWR: 48.04,38.33 33.43,38.33 32.67,39.09 32.67,46.71 33.31,47.34 37.24,47.34 37.75,46.83 38.13,46.83 38.39,47.09 38.39,55.47 36.23,57.63 36.23,73 36.1,73.12 30.13,73.12 28.61,71.6 28.61,28.04 27.72,27.15 24.42,27.15 23.66,27.91 23.66,41.75 23.4,42.01 10.45,42.01 9.56,42.9 9.56,50.77 13.75,54.96 14.89,54.96 15.4,54.45 15.91,54.45 16.04,54.58 16.04,56.36 15.78,56.61 14.38,56.61 12.73,54.96 9.81,54.96 8.16,53.31 8.16,45.95 7.65,45.44 5.88,45.44 5.24,46.07 5.24,58.77 9.3,62.84 18.96,62.84 19.34,63.22 19.34,68.3 22.26,71.22 22.26,71.85 21.37,72.74 21.37,75.66 23.27,77.57 39.78,77.57 40.93,78.71 40.93,82.01 40.42,82.52 19.85,82.52 19.08,83.28 8.67,83.28 7.65,82.27 7.65,79.35 5.37,77.06 2.57,77.06 1.56,76.04 1.56,38.71 1.94,38.33 7.02,38.33 7.65,37.69 7.65,21.94 3.08,17.37 3.08,13.81 3.46,13.43 18.07,13.43 23.91,19.28 47.91,19.28 48.42,19.78 48.42,37.94
3V3_WIFI on TOP: 37.37,76.3 34.45,76.3 34.2,76.04 34.2,75.28 34.45,75.03 34.45,73.89 34.58,73.76 34.83,73.76 34.83,74.65 35.21,75.03 37.37,75.03 37.5,75.16 37.5,76.17
3V3_WIFI on TOP: 31.78,63.98 30.89,63.98 30.51,63.6 30.51,63.34 30.26,63.09 29.37,63.09 29.24,62.96 29.24,62.33 28.99,62.07 28.99,61.06 29.12,60.93 30.89,60.93 31.15,61.19 31.15,62.58 32.04,63.47 32.04,63.73
3V3_WIFI on BOTTOM: 38.51,73.89 36.48,73.89 36.36,74.01 36.36,74.52 35.85,75.03 34.7,75.03 34.58,74.9 34.58,71.35 34.2,70.96 31.53,70.96 31.02,70.46 29.75,70.46 28.99,69.69 28.99,67.66 28.86,67.54 27.72,67.54 27.47,67.79 27.47,71.85 27.72,72.11 30.13,72.11 30.77,72.74 30.77,75.79 31.66,76.68 36.86,76.68 38.77,74.77 38.77,74.14
3V3_WIFI on LYR3: 30.01,61.31 28.74,61.31 28.48,61.57 28.48,71.85 28.61,71.98 30.13,71.98 30.26,71.85 30.26,61.57
3V3_WIFI on LYR4: 34.51,63.28 41.63,63.28 43.34,61.57 43.34,59.79 43.09,59.53 42.58,59.53 41.18,60.93 35.09,60.93 33.94,62.07 31.91,62.07 31.28,61.44 30.01,61.44 29.88,61.57 29.88,62.71 30.51,63.34 34.45,63.34 ; 1 cut-out
5V_DC on BOTTOM: 44.36,32.48 42.07,32.48 41.82,32.74 41.82,34.52 42.32,35.02 42.32,36.42 41.94,36.8 41.94,40.87 41.56,41.25 39.28,41.25 38.13,40.1 36.74,40.1 36.61,40.23 36.61,43.15 38.64,45.18 42.58,45.18 44.1,43.66 44.1,39.34 44.61,38.83 46.13,38.83 47.15,37.82 47.15,35.28 46.52,34.64 45.12,34.64 44.74,34.26 44.74,32.86
5V_IN on TOP: 47.15,42.14 48.04,42.14 48.42,41.75 48.42,39.21 47.91,38.71 47.28,38.71 47.02,38.96 47.02,42.01
5V_IN on BOTTOM: 31.28,45.44 31.28,47.47 31.53,47.72 33.94,47.72 34.45,47.22 34.45,45.56 34.32,45.44 33.82,45.44 33.43,45.06 31.66,45.06
5V_IN on BOTTOM: 26.2,26.9 26.96,26.9 27.08,27.02 27.08,27.78 26.96,27.91 26.07,27.91 25.94,27.78 25.94,27.15
5V_IN on BOTTOM: 48.04,38.96 47.28,38.96 46.9,39.34 44.74,39.34 44.48,39.6 44.48,42.01 44.61,42.14 48.04,42.14 48.29,41.88 48.29,39.21
5V_IN on BOTTOM: 48.93,73.76 52.99,69.69 52.99,60.93 50.58,58.52 48.42,58.52 48.04,58.9 48.04,62.46 48.93,63.34 48.93,71.73 48.04,72.62 46.39,72.62 46.13,72.87 46.13,73.63 46.26,73.76
5V_IN on LYR3: 26.96,26.9 26.45,26.9 26.32,27.02 26.32,28.93 29.5,32.1 37.63,32.1 47.15,41.63 48.29,41.63 48.42,41.5 48.42,38.96 47.91,38.45 47.28,38.45 43.72,34.9 43.72,31.59 41.56,29.44 29.5,29.44
5V_IN on LYR5_PWR: 33.56,46.96 36.74,46.96 37.12,46.58 38.39,46.58 38.77,46.96 38.77,54.45 39.66,55.34 45.25,55.34 46.39,56.49 46.39,59.41 46.77,59.79 49.44,59.79 49.94,59.28 49.94,40.74 48.04,38.83 33.94,38.83 33.05,39.72 33.05,46.45
5V_RPI on BOTTOM: 49.06,74.39 51.09,72.36 54.39,72.36 55.02,73 55.02,76.93 54.52,77.44 52.74,77.44 52.36,77.06 52.36,75.79 52.1,75.54 50.45,75.54 49.69,76.3 46.64,76.3 46.39,76.04 46.39,75.41 46.13,75.16 46.13,74.52 46.26,74.39
5V_USB on BOTTOM: 33.56,35.15 35.85,35.15 36.1,34.9 36.1,33.12 35.85,32.86 33.69,32.86 33.43,33.12 33.43,35.02
5V_USB on BOTTOM: 13.24,31.59 13.24,33.25 13.5,33.5 14.64,33.5 15.4,34.26 16.42,34.26 16.92,33.75 16.92,29.82 16.67,29.56 15.53,29.56 15.27,29.82 15.27,30.58 14.64,31.21 13.62,31.21
5V_USB on LYR4: 35.72,33.88 30.51,33.88 28.86,32.23 15.78,32.23 15.27,31.72 15.27,29.44 15.78,28.93 32.16,28.93 35.85,32.61 35.85,33.75
GND on TOP: 52.74,13.69 52.48,13.43 52.48,11.4 52.87,11.02 54.39,11.02 54.77,10.64 54.77,3.65 53.12,2 43.72,2 42.96,2.77 42.96,5.94 41.31,7.59 41.31,11.15 39.02,13.43 39.02,17.88 38.9,18.01 22.64,18.01 22.26,17.62 22.26,14.96 21.5,14.2 5.62,14.2 4.73,13.31 4.73,2.51 4.35,2.13 1.3,2.13 1.05,2.38 1.05,19.78 1.56,20.29 5.11,20.29 6.64,21.82 6.64,22.07 7.15,22.58 7.15,28.42 6.76,28.8 4.35,28.8 3.72,29.44 3.72,34.77 4.73,35.79 7.02,35.79 7.27,36.04 7.27,37.06 6.51,37.82 1.81,37.82 1.18,38.45 1.18,76.43 2.32,77.57 5.11,77.57 7.15,79.6 7.15,83.16 7.53,83.54 18.96,83.54 19.85,82.65 35.97,82.65 36.48,83.16 36.48,84.55 36.61,84.68 52.61,84.68 54.77,82.52 54.77,27.53 54.14,26.9 51.34,26.9 49.18,24.74 49.18,22.32 52.48,19.02 52.48,17.75 52.74,17.5 54.39,17.5 54.77,17.12 54.77,13.94 54.52,13.69 ; 30 cut-outs
GND on TOP: 28.61,62.84 27.72,62.84 27.34,62.46 27.34,60.93 27.47,60.8 28.23,60.8 28.35,60.93 28.35,61.95 28.74,62.33 28.74,62.71
GND on TOP: 15.15,22.07 16.8,22.07 17.31,21.56 17.31,19.53 16.67,18.89 15.15,18.89 14.64,19.4 14.64,21.56
GND on TOP: 29.24,76.43 28.74,76.43 28.61,76.3 28.61,75.92 28.1,75.41 28.1,74.9 28.23,74.77 28.74,74.77 29.37,75.41 29.37,76.3
GND on TOP: 37.5,76.93 34.58,76.93 33.94,76.3 32.93,76.3 32.67,76.55 32.67,77.31 33.56,78.2 37.24,78.2 37.63,77.82 37.63,77.06
GND on BOTTOM: 31.28,44.55 31.02,44.55 30.51,44.04 30.51,42.52 30.77,42.26 31.91,42.26 32.16,42.01 32.16,38.71 32.29,38.58 33.31,38.58 34.2,39.47 35.72,39.47 36.36,40.1 36.36,45.31 36.23,45.44 34.7,45.44 34.2,44.93 33.31,44.93 33.05,44.68 31.4,44.68
GND on BOTTOM: 15.91,38.71 15.65,38.71 15.4,38.45 15.4,37.44 15.65,37.18 15.65,36.29 15.91,36.04 16.67,36.04 16.8,36.17 16.8,36.8 16.04,37.56 16.04,38.58
GND on BOTTOM: 40.8,36.04 40.42,36.04 40.29,36.17 40.29,40.1 40.04,40.36 39.53,40.36 39.28,40.61 39.28,40.87 39.4,40.99 41.18,40.99 41.44,40.74 41.44,36.93 41.05,36.55 41.05,36.29
GND on BOTTOM: 27.21,26.01 27.21,26.9 27.59,27.28 28.23,27.28 28.61,26.9 28.61,26.39 28.23,26.01 28.23,24.1 29.37,22.96 29.37,22.58 29.24,22.45 28.35,22.45 27.97,22.83 27.97,23.34 27.59,23.72 27.08,23.72 26.96,23.85 26.96,25.75
GND on BOTTOM: 15.4,4.16 11.34,4.16 11.08,4.42 11.08,6.58 11.59,7.08 14.89,7.08 15.65,6.32 15.65,4.42
GND on BOTTOM: 31.15,51.28 31.15,51.91 30.51,52.55 30.13,52.55 29.24,53.44 24.04,53.44 23.91,53.31 23.91,52.8 24.29,52.42 24.29,50.14 24.42,50.01 24.54,50.01 25.31,50.77 26.83,50.77 27.21,50.39 28.48,50.39 28.61,50.52 28.61,50.77 28.23,51.15 28.23,51.79 28.48,52.04 29.37,52.04 29.62,51.79 29.62,51.41 29.75,51.28
GND on BOTTOM: 21.12,51.28 20.48,51.28 20.1,51.66 19.72,51.66 19.59,51.53 19.59,49.5 19.85,49.25 21.24,49.25 21.5,49.5 21.5,50.9
GND on BOTTOM: 42.2,65.25 43.21,65.25 43.98,64.49 43.98,63.09 44.48,62.58 44.48,62.2 44.1,61.82 43.85,61.82 43.34,61.31 41.94,61.31 41.69,61.57 41.69,64.23 41.94,64.49 41.94,65
GND on BOTTOM: 8.92,51.66 11.46,51.66 11.97,51.15 11.97,49.25 11.72,48.99 10.57,48.99 10.45,49.12 10.45,50.39 10.32,50.52 8.8,50.52 8.54,50.77 8.54,51.28
GND on BOTTOM: 47.66,2.51 43.47,2.51 42.96,3.02 42.96,6.58 43.21,6.83 47.53,6.83 48.55,5.81 48.55,3.4
GND on BOTTOM: outline of 86 points within 1.05,1.37 54.77,84.68 ; 36 cut-outs
GND on BOTTOM: 8.8,57.25 9.18,57.25 9.94,56.49 10.96,56.49 11.21,56.23 11.21,54.84 10.83,54.45 10.07,54.45 9.18,55.34 9.18,55.72 8.67,56.23 8.67,57.12
GND on BOTTOM: 26.2,33.5 25.18,33.5 24.8,33.12 24.8,32.36 24.16,31.72 24.16,29.94 24.42,29.69 25.31,29.69 25.56,29.94 25.56,31.34 26.45,32.23 26.45,33.25
GND on BOTTOM: 35.85,24.1 34.32,24.1 34.2,24.23 34.2,25.88 34.58,26.26 38.01,26.26 39.15,27.4 39.15,28.8 39.4,29.05 41.31,29.05 41.82,28.55 44.86,28.55 45.12,28.8 48.04,28.8 48.93,27.91 48.93,17.88 50.33,16.48 50.33,16.1 50.07,15.85 47.02,15.85 46.52,16.35 46.52,17.62 45.88,18.26 44.48,18.26 44.1,18.64 44.1,23.85 42.58,25.37 39.78,25.37 38.77,24.36 36.1,24.36
GND on LYR2_GND: outline of 86 points within 1.05,1.37 54.77,84.68 ; 1 cut-out
GND on LYR3: 49.94,84.68 48.29,84.68 48.04,84.43 47.91,84.43 47.79,84.3 47.79,80.74 47.91,80.62 48.17,80.62 48.17,77.7 48.04,77.57 43.09,77.57 42.96,77.7 42.96,80.62 43.47,80.62 43.47,84.68 36.61,84.68 36.48,84.55 36.48,83.03 36.86,82.65 38.77,82.65 39.28,83.16 40.67,83.16 40.93,82.9 40.93,76.93 38.39,74.39 38.39,72.87 39.02,72.23 40.42,72.23 42.83,69.82 42.83,63.47 43.59,62.71 43.59,58.52 43.98,58.14 48.04,58.14 50.07,60.17 50.07,84.55
GND on LYR4: 48.04,84.68 48.04,84.43 47.79,84.43 47.79,80.62 48.17,80.62 48.17,77.7 48.04,77.57 43.09,77.57 42.96,77.7 42.96,80.62 43.47,80.62 43.47,84.68 36.61,84.68 36.48,84.55 36.48,83.03 36.86,82.65 38.77,82.65 39.28,83.16 40.67,83.16 40.93,82.9 40.93,82.14 40.04,81.25 29.37,81.25 27.34,79.22 27.34,75.92 29.24,74.01 43.34,74.01 43.59,74.27 43.59,75.41 44.1,75.92 47.91,75.92 49.94,77.95 49.94,84.55 49.82,84.68
GND on LYR5_PWR: 52.61,84.68 48.04,84.68 48.04,84.43 47.79,84.43 47.79,80.62 48.17,80.62 48.17,77.7 48.04,77.57 43.09,77.57 42.96,77.7 42.96,80.62 43.47,80.62 43.47,84.68 36.61,84.68 36.48,84.55 36.48,83.03 36.74,82.78 40.55,82.78 41.18,82.14 41.18,76.68 40.67,76.17 40.67,72.74 41.82,71.6 41.82,66.52 39.66,64.36 39.66,60.42 40.04,60.04 54.26,60.04 54.77,60.55 54.77,82.52
GND_EARTH on TOP: outline of 94 points within 0.29,0.35 55.66,84.68
GND_EARTH on BOTTOM, LYR3, LYR4, LYR5_PWR: outline of 96 points within 0.29,0.35 55.66,84.68
GND_EARTH on LYR2_GND: outline of 96 points within 0.29,0.35 55.66,84.68
VBAT on TOP: 49.82,14.7 50.45,15.34 51.6,15.34 51.72,15.21 51.72,14.7 51.6,14.58 50.58,14.58 50.07,14.07 48.55,14.07 48.42,14.2 48.42,14.58 48.55,14.7
VBAT on BOTTOM: 48.42,15.34 50.33,15.34 50.58,15.08 50.58,14.2 50.33,13.94 48.42,13.94 48.17,14.2 48.17,15.08
DC_12V on BOTTOM: 41.94,14.96 39.28,14.96 38.64,15.59 38.64,19.28 37.37,20.55 36.23,20.55 36.1,20.67 36.1,22.45 35.72,22.83 34.96,22.83 34.83,22.96 35.72,22.96 35.85,23.09 37.12,23.09 37.88,23.85 42.45,23.85 43.09,23.21 43.09,21.94 42.32,21.18 42.32,15.34
EXT_12V on BOTTOM: 44.61,17.12 45.25,17.12 47.02,15.34 47.66,15.34 47.91,15.08 47.91,9.62 47.53,9.24 44.23,9.24 43.85,9.62 43.85,16.35
HOST_USB1_VBUS on TOP: 10.57,22.83 9.81,22.83 9.56,22.58 9.56,18.13 9.69,18.01 10.7,18.01 10.83,18.13 10.83,22.58
HOST_USB1_VBUS on BOTTOM: 17.18,24.99 17.05,24.99 16.8,25.24 15.78,25.24 15.65,25.37 15.65,26.9 14.89,27.66 10.7,27.66 9.05,26.01 9.05,20.16 9.3,19.91 9.94,19.91 10.07,20.04 10.07,20.42 10.83,21.18 10.83,25.5 11.72,26.39 14,26.39 14.64,25.75 14.64,24.99 14.89,24.74 16.92,24.74
HOST_USB2_VBUS on TOP: 12.73,18.13 11.59,18.13 11.46,18.26 11.46,21.69 11.84,22.07 12.61,22.07 13.24,21.43 13.24,18.64
HOST_USB2_VBUS on BOTTOM: 16.92,23.85 14.77,23.85 13.5,22.58 12.61,22.58 12.1,22.07 12.1,20.04 12.23,19.91 12.48,19.91 13.24,20.67 13.24,20.8 15.91,23.47 16.92,23.47 17.05,23.59 17.05,23.72
SW on BOTTOM: 35.09,23.72 35.85,23.72 36.36,24.23 37.24,24.23 37.37,24.1 37.37,23.72 36.99,23.34 35.97,23.34 35.85,23.47 35.09,23.47 34.96,23.59
SW on BOTTOM: 30.39,25.12 31.91,25.12 32.55,25.75 32.55,30.83 32.04,31.34 29.37,31.34 28.86,30.83 28.86,27.15 30.13,25.88 30.13,25.37
SW on LYR3: 37.12,23.34 32.67,23.34 30.51,25.5 30.51,27.15 30.89,27.53 35.85,27.53 37.5,25.88 37.5,23.72
VETH1_AVDDH on BOTTOM: 25.94,28.55 25.94,29.18 26.83,30.07 26.83,35.91 27.08,36.17 28.1,36.17 28.48,35.79 28.48,29.69 27.08,28.29 26.2,28.29
VETH1_AVDDH on LYR4: 28.23,32.74 16.8,32.74 14.51,35.02 14.51,35.91 12.86,37.56 12.86,40.48 13.11,40.74 17.69,40.74 19.46,42.52 20.73,42.52 21.12,42.14 21.12,36.67 22.13,35.66 28.23,35.66 28.48,35.4 28.48,32.99
VETH1_AVDDL on TOP: 14.77,40.61 17.31,40.61 17.81,40.1 17.81,37.44 16.8,36.42 14.77,36.42 14,37.18 14,39.85
VETH1_AVDDL on BOTTOM: 14.77,36.55 14.51,36.55 13.75,37.31 13.75,38.58 14,38.83 14.89,38.83 15.02,38.71 15.02,36.8
VETH1_AVDDL_PMOS on TOP: 12.1,52.8 12.73,52.8 13.5,52.04 13.5,50.64 14.26,49.88 14.26,44.04 14.64,43.66 25.18,43.66 25.94,42.9 25.94,41.88 25.05,40.99 14.51,40.99 13.62,40.1 13.62,38.33 12.86,37.56 11.59,37.56 11.08,38.07 11.08,51.79
VETH1_AVDDL_PMOS on BOTTOM: 29.62,34.52 29.62,36.29 27.59,38.33 27.59,41.12 26.45,42.26 24.67,42.26 24.42,42.52 24.42,42.77 24.67,43.02 24.8,43.02 25.94,44.17 28.99,44.17 29.62,43.53 29.62,42.64 30.26,42.01 31.28,42.01 31.78,41.5 31.78,37.31 30.77,36.29 30.77,34.64 30.39,34.26 29.88,34.26
VETH1_AVDDL_PMOS on BOTTOM: 12.23,52.04 13.24,52.04 13.37,52.17 13.37,52.93 13.24,53.06 12.35,53.06 12.1,52.8 12.1,52.17
VETH1_DVDDH on BOTTOM: 22.39,52.55 22.89,52.55 23.02,52.42 23.02,49.5 22.89,49.37 22.26,49.37 22,49.63 22,52.17
VETH1_DVDDH on LYR5_PWR: 22.64,51.03 20.73,51.03 20.1,51.66 20.1,53.18 19.34,53.95 15.53,53.95 14.77,54.71 13.88,54.71 9.81,50.64 9.81,43.15 10.7,42.26 23.15,42.26 23.66,42.77 23.66,44.55 24.67,45.56 24.67,48.99
VETH1_DVDDL on BOTTOM: 13.37,49.25 13.75,48.87 13.75,48.49 13.5,48.23 12.61,48.23 12.35,48.49 12.35,51.53 12.48,51.66 13.24,51.66 13.37,51.53
VETH1_DVDDL on LYR3: 17.18,47.72 19.08,47.72 20.61,46.2 20.61,45.95 20.35,45.69 19.46,45.69 18.7,46.45 14,46.45 13.5,45.95 13.5,41.88 13.11,41.5 11.97,41.5 11.72,41.75 11.72,42.39 11.97,42.64 12.23,42.64 12.48,42.9 12.48,43.15 11.97,43.66 11.97,44.55 12.1,44.68 12.1,45.69 11.84,45.95 11.84,46.58 12.86,47.6 12.86,47.98 12.48,48.36 12.48,48.74 12.73,48.99 15.91,48.99
N3820313 on BOTTOM: 29.37,44.93 26.45,44.93 25.05,46.33 25.05,49.5 25.56,50.01 28.74,50.01 28.99,50.26 31.02,50.26 31.15,50.14 31.15,50.01 31.02,49.88 30.13,49.88 29.88,49.63 29.88,45.44
N3820535 on BOTTOM: 31.02,53.06 30.51,53.06 29.5,54.07 23.78,54.07 23.4,53.69 22.26,53.69 21.5,54.45 21.5,56.23 23.02,57.76 24.29,57.76 24.54,57.5 24.54,56.49 24.8,56.23 30.77,56.23 31.28,55.72 31.28,53.31
N3835690 on TOP: 18.83,21.31 18.07,21.31 17.94,21.18 17.94,19.28 18.19,19.02 18.83,19.02 19.08,19.28 19.08,21.05
N3835690 on LYR3: 17.05,11.4 16.29,11.4 16.04,11.66 16.04,18.39 17.56,19.91 18.58,19.91 18.96,19.53 18.96,19.28 17.43,17.75 17.43,11.78
N3835694 on TOP: 20.73,21.43 20.1,21.43 19.85,21.18 19.85,20.29 19.34,19.78 19.34,18.89 19.46,18.77 20.61,18.77 21.12,19.28 21.12,21.05
N3835694 on LYR4: 20.48,19.53 19.21,19.53 19.08,19.4 19.08,18.13 15.53,14.58 15.53,9.5 16.29,8.73 17.56,8.73 18.32,9.5 18.32,12.93 20.61,15.21 20.61,19.4
N3839488 on BOTTOM: 24.67,27.66 23.78,27.66 23.15,27.02 23.15,25.75 22.51,25.12 21.37,25.12 21.24,24.99 21.24,24.86 21.37,24.74 22.77,24.74 23.53,23.97 24.54,23.97 25.05,24.48 25.05,27.28
N3854640 on TOP: 29.24,76.81 29.62,76.81 30.01,76.43 31.15,76.43 31.28,76.55 31.28,77.19 31.91,77.82 32.67,77.82 32.8,77.95 32.8,78.46 32.67,78.58 30.26,78.58 29.37,77.7 27.72,77.7 27.59,77.57 27.59,77.06 27.72,76.93 29.12,76.93
N3854714 on BOTTOM: 7.4,57.76 12.1,57.76 12.48,58.14 12.48,59.03 12.23,59.28 7.27,59.28 7.15,59.15 7.15,58.01
N3873950 on TOP: 6.76,35.79 7.27,36.29 7.27,37.06 7.4,37.18 8.29,37.18 8.54,36.93 8.54,35.66 8.16,35.28 6.38,35.28 6.38,35.66 6.51,35.79
N3873950 on TOP: 6.64,29.31 8.54,29.31 8.67,29.18 8.67,28.55 8.29,28.17 7.27,28.17 6.51,28.93 6.51,29.18
N3873950 on BOTTOM: 10.83,39.21 7.91,39.21 7.15,38.45 7.15,36.55 7.4,36.29 7.78,36.29 9.3,37.82 10.96,37.82 11.08,37.94 11.08,38.96
N3873950 on LYR3: 7.53,37.18 8.54,37.18 10.19,35.53 10.19,28.67 9.69,28.17 7.78,28.17 7.53,28.42 7.53,30.45 8.92,31.85 8.92,35.15 8.42,35.66 7.78,35.66 7.27,36.17 7.27,36.93
N3874122 on TOP: 6.38,34.9 7.02,34.9 7.27,35.15 8.67,35.15 8.8,35.02 8.8,34.13 8.67,34.01 7.4,34.01 7.02,34.39 6.38,34.39 6.26,34.52 6.26,34.77
N3874122 on BOTTOM: 7.27,35.02 7.27,34.01 7.53,33.75 9.05,33.75 9.81,34.52 10.7,34.52 10.96,34.77 12.23,34.77 12.99,34.01 14.64,34.01 14.89,34.26 14.89,35.91 14,36.8 9.05,36.8
N3991771 on BOTTOM: 30.13,50.9 29.75,50.9 29.5,51.15 29.5,51.41 29.24,51.66 28.61,51.66 28.48,51.53 28.48,51.15 28.86,50.77 28.86,50.52 28.99,50.39 29.88,50.39 30.13,50.64
N3991771 on BOTTOM: 33.43,55.85 35.21,55.85 35.72,55.34 35.72,53.57 35.09,52.93 33.18,52.93 32.93,53.18 32.93,55.34
